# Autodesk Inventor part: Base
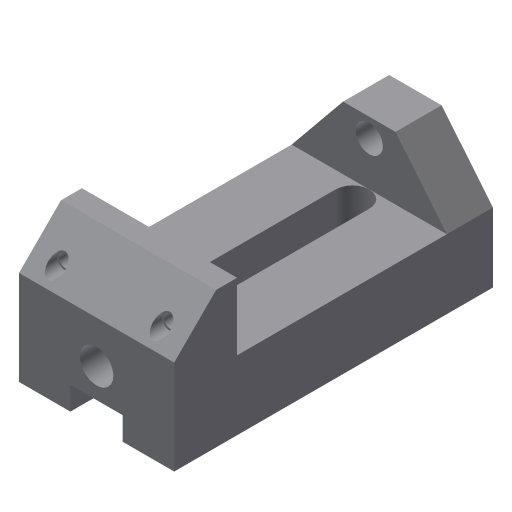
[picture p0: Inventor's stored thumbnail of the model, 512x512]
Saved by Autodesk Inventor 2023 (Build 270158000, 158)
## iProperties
Shininess: 77.0
Length Units: 11269
Angle Units: 11279
Time Units: 11290
Mass Units: 11283
Length Display Precision: 3
Angle Display Precision: 2
Created: 2002-02
Part Number: Base
Document SubType Name: Modeling
Designer: ***
Density: 1 g/cm^3
Material: Generic
Appearance: Default
Density: 0.0
Volumn: 0.0
Area: 0.0
PropertySet Name: Model Information
Control State: 0
Master: False
Checked Out: False
Author: ***
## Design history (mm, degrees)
sketch "Sketch2"
  geometry: L1 (-63.961, -4.254)-(-63.961, -37.254); L2 (-63.961, -37.254)-(88.039, -37.254); L3 (88.039, -37.254)-(88.039, 7.746); L4 (88.039, 7.746)-(68.039, 27.746); L5 (68.039, 27.746)-(58.039, 27.746); L6 (58.039, 27.746)-(58.039, -4.254); L7 (58.039, -4.254)-(-63.961, -4.254)
  constraints: 14 end point, 4 parallel, 1 perpendicular, 1 vertical
  dimensions: "d7" = 10 distance of L4.end L5.end; "d8" = 135 deg angle of L3 L4; "d9" = 33 distance of L1.start L1.end; "d10" = 152 distance of L1.end L2.end; "d11" = 65 distance between parallel lines of L5 L2; "d21" = 30 distance between parallel lines of L3 L6
extrude "Extrusion1" new body sketch "Sketch2" stored distance "d13" = 74; taper "d14" = 0 deg
sketch "Sketch3"
  geometry: L1 (0, 74)-(0, 0) reference; L2 (0, 0)-(-30, 24.5); L3 (-30, 24.5)-(-30, 49.5); L4 (-30, 49.5)-(0, 74); C1 r 6.5 at (-21, 37)
  constraints: 6 end point, 1 centre point, 1 equal length, 1 parallel
  dimensions: "d15" = 25 distance of L2.end L3.end; "d16" = 30 distance between parallel lines of L3 L1; "d17" = 13 diameter of C1; "d18" = 9 distance from line of L3 C1.centre
extrude "Extrusion2" join sketch "Sketch3" distance "d19" = 22; taper "d20" = 0 deg
sketch "Sketch4"
  geometry: L1 (0, 0)-(0, 74) reference; L2 (0, 0)-(45, 0) reference; C1 r 8 at (25, 37)
  constraints: 1 centre point
  dimensions: "d22" = 16 diameter of C1; "d23" = 25 distance from line of L1 C1.centre; "d24" = 37 distance from line of L2 C1.centre
extrude "Extrusion3" cut sketch "Sketch4" distance "d25" = 13; taper "d26" = 0 deg
sketch "Sketch5"
  geometry: L1 (45, 74)-(0, 74) reference; L2 (65, 0)-(65, 74) reference; 1 further point
  dimensions: "d27" = 12 distance from line of point (51, 62) L1; "d28" = 14 distance from line of L2 point (51, 62)
hole "Hole1" sketch "Sketch5" at (51, 62) diameter "d29" = 6; stored, may be unused: countersink angle "d33" = 82 deg, drill point angle "d35" = 0 deg; dims "d30" = 6, "d31" = 8, "d32" = 10, "d34" = 30
mirror "Mirror1"
sketch "Sketch6"
  geometry: L1 (100, 0)-(100, 74) reference; L2 (100, 74)-(0, 74) reference; L3 (14, 45)-(92, 45); L4 (92, 29)-(14, 29); A1 r 8 centre (92, 37) between (92, 29) and (92, 45); A2 r 8 centre (14, 37) between (14, 45) and (14, 29)
  constraints: 4 end point, 4 point on circle, 4 tangent, 2 centre point, 1 horizontal, 1 parallel
  dimensions: "d36" = 8 radius of A2; "d37" = 78 distance of L4.start L4.end; "d38" = 8 distance from line of L1 A1.centre; "d39" = 37 distance from line of L2 A2.centre
extrude "Extrusion4" cut sketch "Sketch6" extent not by distance; stored distance "d40" = 13; taper "d41" = 0 deg
sketch "Sketch7"
  geometry: L1 (0, 49.5)-(11, 49.5); L2 (11, 49.5)-(11, 24.5); L3 (11, 24.5)-(0, 24.5); L4 (0, 24.5)-(0, 49.5); L5 (45, 74)-(0, 74) reference; L6 (0, 0)-(0, 74) reference
  constraints: 8 end point, 2 parallel, 1 collinear, 1 horizontal, 1 perpendicular
  dimensions: "d42" = 25 distance of L3.end L1.start; "d43" = 11 distance of L1.start L1.end; "d44" = 24.5 distance between parallel lines of L5 L1
extrude "Extrusion5" cut sketch "Sketch7" extent not by distance; stored distance "d45" = 13; taper "d46" = 0 deg
body "Solid1"
